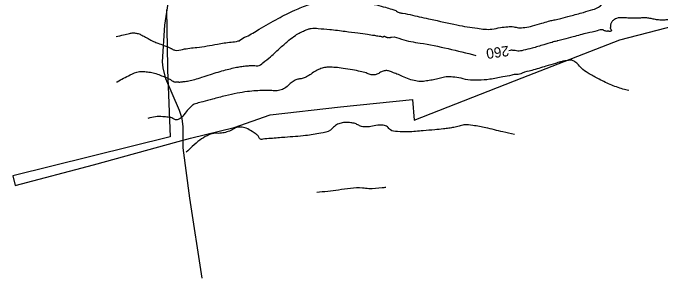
# Model space of a CAD drawing. Extents: x -478645 to -472650, y -1118147 to -1113892.
# Drawn here: x -475693.2 to -475440.9, y -1116598.8 to -1116495.4 of the extents above; entities that cross this region are included whole.
import ezdxf

# ---------------------------------------------------------------- set-up
doc = ezdxf.new("R2010")
doc.units = 0
for name, color, linetype in [('ObPÚ', 7, 'Continuous'), ('plyn_ntl', 7, 'Continuous'), ('Vrstevnice_hlavni', 7, 'Continuous'), ('Vrstevnice_popis', 7, 'Continuous'), ('Vrstevnice_vedlejsi', 7, 'Continuous')]:
    doc.layers.add(name, color=color, linetype=linetype)

msp = doc.modelspace()

# ---------------------------------------------------------------- linework, layer by layer
at = {"layer": 'ObPÚ'}
msp.add_lwpolyline([(-475633.34, -1116494.11), (-475632.95, -1116516.38), (-475632.91, -1116517.49), (-475631.84, -1116543.64), (-475693.15, -1116558.84), (-475692.22, -1116562.71), (-475661.8, -1116554.61), (-475628.73, -1116545.53), (-475623.88, -1116544.22), (-475606.95, -1116539.98), (-475592.9, -1116535.1), (-475565.4, -1116531.92), (-475537.31, -1116529.08), (-475536.71, -1116537.24), (-475494.68, -1116520.66), (-475456.5, -1116505.83), (-475409.35, -1116493.62)], dxfattribs=at)
at = {"layer": 'plyn_ntl'}
msp.add_lwpolyline([(-475619.36, -1116598.76), (-475624.14, -1116567.57), (-475626.84, -1116548.02), (-475626.83, -1116539.78), (-475627.23, -1116536.54), (-475628.25, -1116533.35), (-475633.54, -1116521.09), (-475634.62, -1116516.81), (-475634.82, -1116514.43), (-475633.94, -1116500.19), (-475632.63, -1116491.62), (-475638.81, -1116490.59), (-475649.17, -1116491.03)], dxfattribs=at)
at = {"layer": 'Vrstevnice_hlavni'}
for points in [[(-475269.744, -1116537.748), (-475276.55, -1116536.907), (-475282.831, -1116534.78), (-475291.988, -1116530.947), (-475304.021, -1116525.407), (-475312.333, -1116521.565), (-475316.923, -1116519.42), (-475317.791, -1116518.972), (-475318.518, -1116518.618), (-475319.106, -1116518.359), (-475319.553, -1116518.195), (-475323.73, -1116517.446), (-475331.638, -1116516.112), (-475343.276, -1116514.192), (-475351.605, -1116512.902), (-475356.626, -1116512.244), (-475358.338, -1116512.215), (-475360.019, -1116512.226), (-475361.669, -1116512.277), (-475363.289, -1116512.368), (-475365.701, -1116512.113), (-475368.907, -1116511.513), (-475372.905, -1116510.568), (-475376.771, -1116509.696), (-475380.503, -1116508.899), (-475384.102, -1116508.175), (-475387.388, -1116507.8), (-475390.362, -1116507.772), (-475393.023, -1116508.092), (-475395.275, -1116508.283), (-475397.118, -1116508.344), (-475398.551, -1116508.277), (-475399.891, -1116508.328), (-475401.138, -1116508.498), (-475402.292, -1116508.788), (-475403.351, -1116508.942), (-475404.317, -1116508.96), (-475405.188, -1116508.842), (-475406.461, -1116508.119), (-475408.134, -1116506.791), (-475410.209, -1116504.858), (-475412.336, -1116503.609), (-475414.514, -1116503.044), (-475416.743, -1116503.163), (-475418.444, -1116502.905), (-475419.617, -1116502.271), (-475420.262, -1116501.261), (-475421.839, -1116500.271), (-475424.347, -1116499.301), (-475427.788, -1116498.352), (-475430.64, -1116497.77), (-475432.904, -1116497.555), (-475434.578, -1116497.706), (-475436.216, -1116497.856), (-475437.817, -1116498.006), (-475439.382, -1116498.155), (-475440.997, -1116498.127), (-475442.664, -1116497.923), (-475444.381, -1116497.541), (-475446.064, -1116497.329), (-475447.712, -1116497.287), (-475449.325, -1116497.415), (-475451.077, -1116497.448), (-475452.97, -1116497.386), (-475455.003, -1116497.23), (-475456.614, -1116497.255), (-475457.803, -1116497.462), (-475458.57, -1116497.851), (-475459.162, -1116498.249), (-475459.578, -1116498.659), (-475459.819, -1116499.078), (-475459.999, -1116499.521), (-475460.121, -1116499.986), (-475460.183, -1116500.474), (-475460.225, -1116500.856), (-475460.247, -1116501.131), (-475460.249, -1116501.299), (-475460.175, -1116501.502), (-475460.024, -1116501.74), (-475459.797, -1116502.012), (-475459.779, -1116502.238), (-475459.969, -1116502.418), (-475460.368, -1116502.55), (-475460.654, -1116502.61), (-475460.827, -1116502.599), (-475460.888, -1116502.515), (-475461.037, -1116502.478), (-475461.275, -1116502.486), (-475461.603, -1116502.541), (-475462.016, -1116502.479), (-475462.516, -1116502.301), (-475463.101, -1116502.007), (-475465.34, -1116502.308), (-475469.233, -1116503.205), (-475474.78, -1116504.696), (-475478.617, -1116505.714), (-475480.746, -1116506.258)], [(-475652.739, -1116522.291), (-475652.536, -1116522.181), (-475647.467, -1116519.549), (-475643.866, -1116518.238), (-475641.731, -1116518.248), (-475639.573, -1116518.515), (-475637.391, -1116519.039), (-475635.186, -1116519.822), (-475633.397, -1116520.543), (-475632.025, -1116521.204), (-475631.07, -1116521.804), (-475630.311, -1116522.176), (-475629.748, -1116522.319), (-475629.382, -1116522.235), (-475629.057, -1116522.206), (-475628.772, -1116522.232), (-475628.529, -1116522.312), (-475627.757, -1116522.271), (-475626.454, -1116522.108), (-475624.622, -1116521.824), (-475622.298, -1116521.271), (-475619.481, -1116520.449), (-475616.172, -1116519.359), (-475613.102, -1116518.411), (-475610.272, -1116517.604), (-475607.682, -1116516.94), (-475605.387, -1116516.444), (-475603.385, -1116516.115), (-475601.678, -1116515.953), (-475600.167, -1116515.877), (-475598.853, -1116515.888), (-475597.735, -1116515.985), (-475595.685, -1116514.837), (-475592.701, -1116512.442), (-475588.784, -1116508.8), (-475585.55, -1116506.019), (-475582.998, -1116504.096), (-475581.128, -1116503.032), (-475579.491, -1116502.224), (-475578.086, -1116501.67), (-475576.913, -1116501.373), (-475574.106, -1116501.413), (-475569.666, -1116501.793), (-475563.591, -1116502.511), (-475558.664, -1116503.131), (-475554.884, -1116503.654), (-475552.251, -1116504.079), (-475550.428, -1116504.388), (-475549.415, -1116504.582), (-475549.212, -1116504.659), (-475549.018, -1116504.674), (-475548.832, -1116504.628), (-475548.654, -1116504.52), (-475548.476, -1116504.471), (-475548.296, -1116504.479), (-475548.115, -1116504.546), (-475547.883, -1116504.638), (-475547.599, -1116504.755), (-475547.265, -1116504.897), (-475546.943, -1116504.98), (-475546.635, -1116505.005), (-475546.34, -1116504.97), (-475546.055, -1116504.924), (-475545.78, -1116504.865), (-475545.515, -1116504.794), (-475541.714, -1116505.545), (-475534.378, -1116507.116), (-475512.635, -1116511.9)], [(-475480.746, -1116506.258), (-475481.165, -1116506.33), (-475482.97, -1116506.828), (-475486.161, -1116507.752), (-475490.738, -1116509.103), (-475494.134, -1116509.936), (-475496.351, -1116510.253), (-475497.387, -1116510.051), (-475498.231, -1116509.946), (-475498.882, -1116509.938), (-475499.799, -1116510.113)]]:
    msp.add_spline(points, degree=3, dxfattribs=at)
at = {"layer": 'Vrstevnice_vedlejsi'}
for points in [[(-475630.528, -1116509.691), (-475630.007, -1116509.864), (-475626.989, -1116509.564), (-475621.474, -1116508.793), (-475613.463, -1116507.55), (-475608.097, -1116506.713), (-475605.376, -1116506.282), (-475605.3, -1116506.257), (-475605.23, -1116506.235), (-475605.165, -1116506.217), (-475605.106, -1116506.201), (-475605.053, -1116506.19), (-475605.007, -1116506.182), (-475604.968, -1116506.179), (-475604.933, -1116506.177), (-475604.903, -1116506.177), (-475604.877, -1116506.179), (-475604.83, -1116506.153), (-475604.762, -1116506.098), (-475604.672, -1116506.014), (-475602.142, -1116504.554), (-475597.172, -1116501.716), (-475589.762, -1116497.5), (-475583.273, -1116494.296), (-475577.705, -1116492.104), (-475573.058, -1116490.924), (-475568.445, -1116490.316), (-475563.866, -1116490.281), (-475559.321, -1116490.818), (-475555.147, -1116491.476), (-475551.343, -1116492.255), (-475547.911, -1116493.155), (-475545.418, -1116493.891), (-475543.864, -1116494.463), (-475543.25, -1116494.872), (-475542.612, -1116495.173), (-475541.951, -1116495.364), (-475541.266, -1116495.447), (-475537.384, -1116496.256), (-475530.304, -1116497.792), (-475520.026, -1116500.053), (-475512.065, -1116501.349), (-475506.421, -1116501.678), (-475503.094, -1116501.042), (-475500.256, -1116500.739), (-475497.906, -1116500.767), (-475496.045, -1116501.129), (-475493.603, -1116501.015), (-475490.578, -1116500.425), (-475486.971, -1116499.361), (-475484.303, -1116498.606), (-475482.573, -1116498.162), (-475481.781, -1116498.027), (-475479.535, -1116497.475), (-475475.835, -1116496.507), (-475470.682, -1116495.121), (-475467.008, -1116494), (-475464.813, -1116493.142), (-475464.098, -1116492.548), (-475463.472, -1116491.893), (-475462.937, -1116491.178), (-475462.493, -1116490.402), (-475460.206, -1116488.876), (-475456.077, -1116486.601), (-475450.106, -1116483.577), (-475446.093, -1116481.539), (-475444.037, -1116480.486), (-475443.94, -1116480.419), (-475443.594, -1116480.1), (-475442.999, -1116479.529), (-475442.156, -1116478.706), (-475439.818, -1116478.107), (-475435.984, -1116477.731), (-475430.655, -1116477.578), (-475425.047, -1116478.564), (-475419.159, -1116480.687), (-475412.992, -1116483.949), (-475408.776, -1116486.795), (-475406.513, -1116489.224), (-475406.202, -1116491.237), (-475405.448, -1116492.521), (-475404.251, -1116493.078), (-475402.612, -1116492.906), (-475400.508, -1116492.903), (-475397.939, -1116493.069), (-475394.905, -1116493.403), (-475392.586, -1116493.437), (-475390.982, -1116493.169), (-475390.093, -1116492.599), (-475388.995, -1116491.864), (-475387.688, -1116490.963), (-475386.173, -1116489.896), (-475385.094, -1116489.163), (-475384.453, -1116488.764), (-475384.249, -1116488.7), (-475383.904, -1116488.658), (-475383.417, -1116488.637)], [(-475652.947, -1116504.61), (-475650.015, -1116503.87), (-475647.681, -1116503.339), (-475646.401, -1116503.133), (-475645.044, -1116503.247), (-475643.611, -1116503.678), (-475642.102, -1116504.428), (-475640.906, -1116505.061), (-475640.023, -1116505.575), (-475639.452, -1116505.971), (-475638.315, -1116506.506), (-475636.61, -1116507.181), (-475634.337, -1116507.995), (-475632.71, -1116508.616), (-475631.726, -1116509.045), (-475631.388, -1116509.282), (-475630.988, -1116509.497), (-475630.528, -1116509.691)], [(-475453.074, -1116525.647), (-475455.344, -1116525.027), (-475460.296, -1116523.253), (-475465.161, -1116520.914), (-475468.908, -1116518.799), (-475471.535, -1116516.907), (-475473.044, -1116515.239), (-475474.39, -1116514.184), (-475475.573, -1116513.741), (-475476.593, -1116513.911), (-475477.295, -1116514.014), (-475477.678, -1116514.049), (-475477.743, -1116514.016), (-475477.993, -1116514.049), (-475478.427, -1116514.149), (-475479.046, -1116514.316), (-475479.474, -1116514.429), (-475479.711, -1116514.49), (-475479.758, -1116514.498), (-475481.638, -1116515.049), (-475485.351, -1116516.143), (-475490.898, -1116517.78), (-475494.666, -1116518.858), (-475496.656, -1116519.377), (-475496.869, -1116519.335), (-475498.698, -1116519.631), (-475502.146, -1116520.263), (-475507.21, -1116521.231), (-475511.761, -1116521.618), (-475515.798, -1116521.425), (-475519.321, -1116520.649), (-475522.361, -1116520.317), (-475524.919, -1116520.428), (-475526.996, -1116520.982), (-475529.149, -1116521.441), (-475531.379, -1116521.805), (-475533.687, -1116522.074), (-475536.099, -1116521.883), (-475538.614, -1116521.232), (-475541.232, -1116520.121), (-475543.45, -1116519.205), (-475545.267, -1116518.486), (-475546.683, -1116517.962), (-475548.09, -1116517.894), (-475549.488, -1116518.283), (-475550.877, -1116519.126), (-475552.332, -1116519.488), (-475553.854, -1116519.367), (-475555.443, -1116518.763), (-475557.728, -1116518.163), (-475560.707, -1116517.567), (-475564.381, -1116516.973), (-475567.432, -1116516.627), (-475569.859, -1116516.528), (-475571.664, -1116516.676), (-475573.524, -1116517.225), (-475575.44, -1116518.176), (-475577.412, -1116519.529), (-475579.174, -1116520.485), (-475580.727, -1116521.043), (-475582.071, -1116521.203), (-475583.519, -1116521.823), (-475585.071, -1116522.904), (-475586.728, -1116524.444), (-475588.568, -1116525.406), (-475590.594, -1116525.792)], [(-475590.594, -1116525.792), (-475592.803, -1116525.599), (-475595.401, -1116525.578), (-475598.388, -1116525.727), (-475601.763, -1116526.047), (-475605.72, -1116526.697), (-475610.259, -1116527.679), (-475615.38, -1116528.992), (-475619.126, -1116529.977), (-475621.498, -1116530.634), (-475622.495, -1116530.962), (-475623.729, -1116531.893), (-475625.198, -1116533.425), (-475626.904, -1116535.559), (-475628.415, -1116536.777), (-475629.729, -1116537.08), (-475630.849, -1116536.468), (-475632.53, -1116536.055), (-475634.773, -1116535.843), (-475637.577, -1116535.831), (-475640.508, -1116536.541)], [(-475497.631, -1116542.745), (-475502.155, -1116541.772), (-475508.773, -1116540.151), (-475513.825, -1116539.239), (-475517.311, -1116539.038), (-475519.23, -1116539.546), (-475521.209, -1116539.978), (-475523.249, -1116540.334), (-475525.348, -1116540.612), (-475528.679, -1116540.941), (-475533.239, -1116541.319), (-475539.031, -1116541.747), (-475543.279, -1116541.633), (-475545.983, -1116540.976), (-475547.143, -1116539.777), (-475548.8, -1116539.164), (-475550.953, -1116539.136), (-475553.604, -1116539.694), (-475555.83, -1116539.825), (-475557.633, -1116539.529), (-475559.012, -1116538.806), (-475560.58, -1116538.326), (-475562.338, -1116538.09), (-475564.285, -1116538.096), (-475566.111, -1116538.594), (-475567.816, -1116539.583), (-475569.401, -1116541.063), (-475573.143, -1116542.271), (-475579.04, -1116543.208), (-475587.094, -1116543.873), (-475592.664, -1116544.34), (-475595.75, -1116544.61), (-475596.352, -1116544.681), (-475596.833, -1116544.521), (-475597.192, -1116544.129), (-475597.431, -1116543.505), (-475598.345, -1116542.665), (-475599.934, -1116541.611), (-475602.198, -1116540.342), (-475604.33, -1116539.851), (-475606.331, -1116540.139)], [(-475606.331, -1116540.139), (-475608.2, -1116541.205), (-475610.244, -1116541.929), (-475612.464, -1116542.309), (-475614.858, -1116542.346), (-475617.452, -1116543.223), (-475620.245, -1116544.939), (-475623.238, -1116547.495), (-475625.554, -1116549.615)], [(-475547.81, -1116563.462), (-475549.165, -1116563.597), (-475554.381, -1116563.899), (-475556.89, -1116563.665), (-475566.175, -1116564.45), (-475574.674, -1116565.38)]]:
    msp.add_spline(points, degree=3, dxfattribs=at)

# ---------------------------------------------------------------- texts
at = {"layer": 'Vrstevnice_popis'}
msp.add_text(' 260 ', height=4, rotation=187.99493, dxfattribs=at).set_placement((-475498.57, -1116507.923))

doc.saveas('drawing.dxf')
